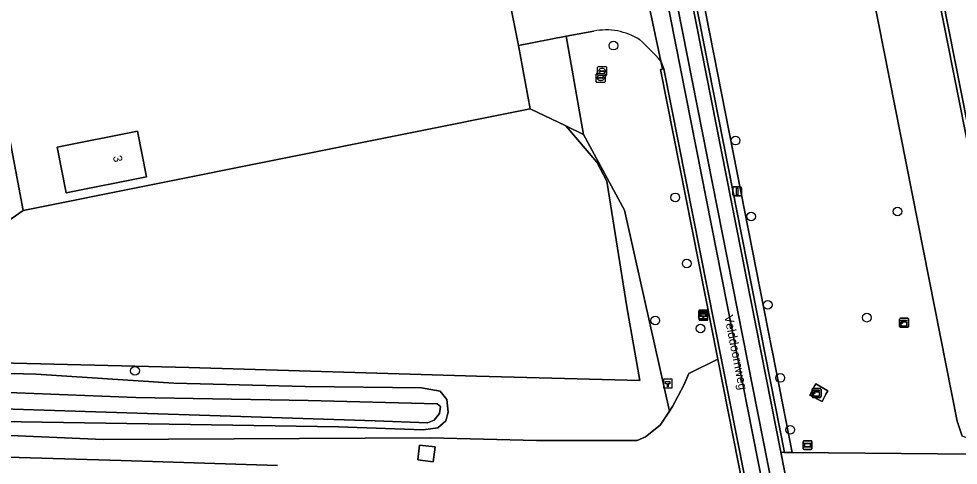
# Model space of a CAD drawing. Extents: x 160203 to 161530, y 379528 to 381797.
# Drawn here: x 160889.3 to 160995.1, y 379661.9 to 379712.2 of the extents above; entities that cross this region are included whole.
import ezdxf

# ---------------------------------------------------------------- set-up
doc = ezdxf.new("R2010")
doc.units = 0
for name, color, linetype in [('IMGEO_Berm_open', 7, 'Continuous'), ('IMGEO_Boom', 7, 'Continuous'), ('IMGEO_Brandkraan', 7, 'Continuous'), ('IMGEO_Erf', 7, 'Continuous'), ('IMGEO_Fietspad_open', 7, 'Continuous'), ('IMGEO_Grasland_overig', 7, 'Continuous'), ('IMGEO_Groenvoorziening', 7, 'Continuous'), ('IMGEO_Hectometerpaal', 7, 'Continuous'), ('IMGEO_Hek', 7, 'Continuous'), ('IMGEO_Kast', 7, 'Continuous'), ('IMGEO_Lichtmast', 7, 'Continuous'), ('IMGEO_Loofbos', 7, 'Continuous'), ('IMGEO_Openbare_ruimte_label', 7, 'Continuous'), ('IMGEO_Pand', 7, 'Continuous'), ('IMGEO_Pand_nummerreeks', 7, 'Continuous'), ('IMGEO_Rijbaan_lokaal_gesloten', 7, 'Continuous'), ('IMGEO_Rijbaan_lokaal_open', 7, 'Continuous'), ('IMGEO_Voetpad_open', 7, 'Continuous'), ('IMGEO_Wegwijzer', 7, 'Continuous')]:
    doc.layers.add(name, color=color, linetype=linetype)

msp = doc.modelspace()

# ---------------------------------------------------------------- linework, layer by layer
at = {"layer": 'IMGEO_Berm_open'}
for points in [[(160977.01, 379644.98), (160931.19, 379877.16)], [(160930.17, 379876.91), (160975.99, 379644.84)]]:
    msp.add_lwpolyline(points, dxfattribs=at)
at = {"layer": 'IMGEO_Boom'}
for centre in [(160956.25, 379709.18), (160970.01, 379698.49), (160963.22, 379692.1), (160988.22, 379690.51), (160971.76, 379689.95), (160964.5, 379684.65), (160973.62, 379680.01), (160960.97, 379678.24), (160984.77, 379678.56), (160966.06, 379677.33), (160902.4, 379672.57), (160975.04, 379671.77), (160976.16, 379665.93)]:
    msp.add_circle(centre, 0.489, dxfattribs=at)
at = {"layer": 'IMGEO_Brandkraan'}
for p, q in [((160954.48, 379705.89), (160954.48, 379706.75)), ((160954.56, 379706.82), (160955.41, 379706.82)), ((160955.48, 379706.75), (160955.48, 379705.89)), ((160954.32, 379705.12), (160954.32, 379705.98)), ((160954.39, 379706.05), (160955.25, 379706.05)), ((160955.41, 379705.82), (160954.56, 379705.82)), ((160954.74, 379706.31), (160954.74, 379706.33)), ((160955.18, 379706.28), (160954.78, 379706.28)), ((160954.79, 379706.36), (160955.18, 379706.36)), ((160954.81, 379705.83), (160954.83, 379705.83)), ((160954.97, 379706.6), (160955, 379706.6)), ((160954.99, 379706.04), (160954.97, 379706.04)), ((160955.23, 379706.33), (160955.23, 379706.31)), ((160955.32, 379705.98), (160955.32, 379705.12)), ((160955.25, 379705.05), (160954.39, 379705.05)), ((160954.58, 379705.54), (160954.58, 379705.56)), ((160954.62, 379705.59), (160955.02, 379705.59)), ((160955.01, 379705.51), (160954.62, 379705.51)), ((160954.83, 379705.27), (160954.8, 379705.27)), ((160955.06, 379705.56), (160955.06, 379705.54))]:
    msp.add_line(p, q, dxfattribs=at)
for points in [[(160954.48, 379705.89), (160954.48, 379706.75)], [(160954.56, 379706.82), (160955.41, 379706.82)], [(160955.48, 379706.75), (160955.48, 379705.89)], [(160954.32, 379705.12), (160954.32, 379705.98)], [(160954.39, 379706.05), (160955.25, 379706.05)], [(160955.41, 379705.82), (160954.56, 379705.82)], [(160955.32, 379705.98), (160955.32, 379705.12)], [(160955.25, 379705.05), (160954.39, 379705.05)]]:
    msp.add_lwpolyline(points, dxfattribs=at)
for centre, radius, start, end in [((160954.56, 379706.74), 0.0765, 91.552, 178.448), ((160954.56, 379706.74), 0.0765, 91.552, 178.448), ((160955.41, 379706.74), 0.0765, 1.552, 88.448), ((160955.41, 379706.74), 0.0765, 1.552, 88.448), ((160954.39, 379705.98), 0.0765, 91.552, 178.448), ((160954.39, 379705.98), 0.0765, 91.552, 178.448), ((160954.56, 379705.89), 0.0765, 181.552, 268.448), ((160954.56, 379705.89), 0.0765, 181.552, 268.448), ((160954.78, 379706.32), 0.0403, 85.8775, 175.7526), ((160954.78, 379706.31), 0.0366, 178.938, 274.7102), ((160955.19, 379706.32), 0.0386, 1.7309, 96.639), ((160955.18, 379706.32), 0.043, 264.8664, 352.4533), ((160955.24, 379705.98), 0.0765, 1.552, 88.448), ((160955.24, 379705.98), 0.0765, 1.552, 88.448), ((160955.41, 379705.89), 0.0765, 271.552, 358.448), ((160955.41, 379705.89), 0.0765, 271.552, 358.448), ((160954.39, 379705.13), 0.0765, 181.552, 268.448), ((160954.39, 379705.13), 0.0765, 181.552, 268.448), ((160954.62, 379705.55), 0.0403, 85.8775, 175.7526), ((160954.61, 379705.54), 0.0366, 178.938, 274.7102), ((160955.02, 379705.55), 0.043, 264.8664, 352.4533), ((160955.02, 379705.56), 0.0386, 1.7309, 96.639), ((160955.24, 379705.13), 0.0765, 271.552, 358.448), ((160955.24, 379705.13), 0.0765, 271.552, 358.448)]:
    msp.add_arc(centre, radius, start, end, dxfattribs=at)
for centre, major_axis, ratio, start_param, end_param in [((160954.81, 379705.55), (-0.387, 0.002), 0.722429, 4.712389, 7.853982), ((160954.97, 379706.32), (-0.387, 0.002), 0.722429, 4.712389, 7.853982), ((160954.83, 379705.55), (-0.39, 0.002), 0.717154, 1.570796, 4.712389), ((160954.99, 379706.32), (-0.39, 0.002), 0.717154, 1.570796, 4.712389)]:
    msp.add_ellipse(centre, major_axis=major_axis, ratio=ratio, start_param=start_param, end_param=end_param, dxfattribs=at)
at = {"layer": 'IMGEO_Erf'}
for points in [[(160945.57, 379709.21), (160944.72, 379713.51), (160938.84, 379743.37), (160882.02, 379731.98), (160889.82, 379690.64), (160946.9, 379702.08)], [(160894.67, 379692.62), (160893.65, 379697.75), (160902.69, 379699.55), (160903.71, 379694.42)]]:
    msp.add_lwpolyline(points, close=True, dxfattribs=at)
at = {"layer": 'IMGEO_Fietspad_open'}
msp.add_lwpolyline([(161063.74, 379662.75), (161006.45, 379663.11), (161000.99, 379663.16), (160976.37, 379663.39), (160975.52, 379663.39), (160975.09, 379663.4), (160975.92, 379659.23), (160976.32, 379659.23), (160998.67, 379659.17), (161063.76, 379658.82)], dxfattribs=at)
at = {"layer": 'IMGEO_Grasland_overig'}
for points in [[(161089.29, 379874.82), (161088.06, 379883.66), (161097.99, 379885.6), (161095.06, 379898.6), (161067.76, 379903.29), (161066.72, 379897.25), (161064.96, 379897.55), (161064.27, 379901.09), (161048.67, 379898.05), (161049.44, 379894.12), (161037.66, 379891.83), (161037.23, 379894.01), (161021.55, 379891.08), (161008.69, 379888.67), (161005.82, 379890.02), (161000, 379888.88), (160960.29, 379881.14), (160984.65, 379758.21), (161001.9, 379671.16), (161088.81, 379688.39), (161124.8, 379695.53), (161114.01, 379750)], [(160934.22, 379662.54), (160934.42, 379664.21), (160936.18, 379664), (160935.97, 379662.32)]]:
    msp.add_lwpolyline(points, close=True, dxfattribs=at)
for points in [[(160840.36, 379818.7), (160816.73, 379790.12), (160856.72, 379758.62), (160866.07, 379730.92), (160881.55, 379684.93), (160889.82, 379690.64), (160882.02, 379731.98), (160938.84, 379743.37), (160943.64, 379744.33), (160939.89, 379764.64), (160934.91, 379791.64)], [(160971.5, 379656.22), (160968, 379673.87), (160964.76, 379672.27), (160964.17, 379670.97), (160962.9, 379668.56), (160962.56, 379668.04), (160961.52, 379666.45), (160959.86, 379665.14), (160958.91, 379664.75), (160947.59, 379664.74), (160935.67, 379665.03), (160898.81, 379664.84), (160883.98, 379665.5), (160868.89, 379665.98), (160828.06, 379666.96), (160812.93, 379667.08), (160784.17, 379667.9), (160765.94, 379668.23)], [(160768.72, 379665.89), (160783.83, 379665.68), (160798.49, 379665.21), (160840.84, 379664.24), (160900.83, 379662.49), (160918.44, 379661.9)]]:
    msp.add_lwpolyline(points, dxfattribs=at)
at = {"layer": 'IMGEO_Groenvoorziening'}
for points in [[(161124.8, 379695.53), (161088.81, 379688.39), (161001.9, 379671.16), (160984.65, 379758.21), (160960.29, 379881.14), (160959.82, 379881.05), (160959.92, 379880.51), (160960.04, 379879.9), (160973.15, 379813.39), (160984.11, 379758.57), (160985.83, 379750), (161000, 379678.61), (161001.69, 379670.67), (161089.34, 379688.04), (161125.46, 379695.28), (161122.82, 379708.52), (161121.99, 379712.67), (161114.55, 379750), (161114.01, 379750)], [(160933, 379878.98), (160975.52, 379663.39), (160976.37, 379663.39), (160974.15, 379674.69), (160974.08, 379675.03), (160933.99, 379879.07)], [(160980.18, 379669.95), (160979.75, 379669.14), (160978.36, 379669.85), (160978.94, 379670.92), (160979.04, 379671.1), (160980.4, 379670.34)]]:
    msp.add_lwpolyline(points, close=True, dxfattribs=at)
for points in [[(160933.99, 379879.07), (160974.08, 379675.03), (160974.15, 379674.69), (160976.37, 379663.39), (161000.99, 379663.16), (161006.45, 379663.11), (161063.74, 379662.75)], [(161142.92, 379692.64), (161145.98, 379696.54), (161138.27, 379693.24), (161136.23, 379692.23), (161130.68, 379689.47), (161118.14, 379687.03), (161106.5, 379683.85), (161096.48, 379679.04), (161085.04, 379672.67), (161070.4, 379668.01), (161059.14, 379666.39), (161049.4, 379665.53), (161034.57, 379663.65), (161025.83, 379663.99), (161019.86, 379665.34), (161017.76, 379665.27), (161013.76, 379664.34), (161011.91, 379663.38), (161000.99, 379663.27), (160995.51, 379665.23), (160994.95, 379666.91), (160953.02, 379879)], [(160954.03, 379710.81), (160950.95, 379710.23), (160952.89, 379699.18), (160957.49, 379690.67), (160962.56, 379668.04), (160962.9, 379668.56), (160964.17, 379670.97), (160964.76, 379672.27), (160968, 379673.87), (160961.55, 379706.48)], [(160961.55, 379706.48), (160961.79, 379706.53), (160961.6, 379707.42)], [(160883.98, 379665.5), (160898.81, 379664.84), (160935.67, 379665.03), (160947.59, 379664.74), (160958.91, 379664.75), (160959.86, 379665.14), (160961.52, 379666.45), (160962.56, 379668.04), (160957.49, 379690.67), (160952.89, 379699.18), (160950.89, 379700.14), (160954.39, 379696.07), (160955.51, 379693.91), (160957.77, 379679.76), (160959.24, 379671.47), (160940.83, 379671.98), (160908.47, 379672.95), (160882.6, 379673.6)], [(160758.24, 379671.16), (160779.42, 379670.28), (160787.45, 379670.4), (160800.46, 379670.24), (160856, 379668.81), (160885.15, 379668.38), (160929.42, 379666.96), (160935.32, 379666.72), (160936.09, 379667.02), (160936.67, 379667.77), (160936.8, 379668.56), (160936.41, 379668.85), (160921.88, 379669.22), (160902.49, 379669.56), (160883.33, 379670.33), (160865.8, 379671.12), (160822.07, 379671.95), (160792.15, 379672.79), (160782.51, 379673.2), (160766.24, 379673.54)], [(160766.24, 379673.54), (160782.51, 379673.2), (160792.15, 379672.79), (160822.07, 379671.95), (160865.8, 379671.12), (160883.33, 379670.33), (160902.49, 379669.56), (160921.88, 379669.22), (160936.41, 379668.85), (160936.8, 379668.56), (160936.67, 379667.77), (160936.09, 379667.02), (160935.32, 379666.72), (160929.42, 379666.96), (160885.15, 379668.38), (160856, 379668.81), (160800.46, 379670.24), (160787.45, 379670.4), (160779.42, 379670.28), (160758.24, 379671.16)], [(160842.51, 379673.48), (160891.29, 379672.2), (160906.77, 379671.18), (160921.57, 379670.82), (160934.64, 379670.66), (160936.75, 379670.28), (160937.49, 379669.34), (160937.67, 379667.93), (160937.38, 379666.93), (160936.5, 379666.16), (160934.84, 379665.92), (160925.29, 379666.27), (160875.27, 379667.07)], [(160875.27, 379667.07), (160925.29, 379666.27), (160934.84, 379665.92), (160936.5, 379666.16), (160937.38, 379666.93), (160937.67, 379667.93), (160937.49, 379669.34), (160936.75, 379670.28), (160934.64, 379670.66), (160921.57, 379670.82), (160906.77, 379671.18), (160891.29, 379672.2), (160842.51, 379673.48)], [(160918.44, 379661.9), (160900.83, 379662.49), (160840.84, 379664.24), (160798.49, 379665.21), (160783.83, 379665.68), (160768.72, 379665.89)]]:
    msp.add_lwpolyline(points, dxfattribs=at)
for centre, radius, start, end in [((160955.42, 379703.88), 7.07, 57.5977, 101.3115), ((160942.12, 379690.63), 25.72, 40.7712, 48.3733)]:
    msp.add_arc(centre, radius, start, end, dxfattribs=at)
at = {"layer": 'IMGEO_Hectometerpaal'}
for p, q in [((160966.79, 379679.26), (160965.95, 379679.26)), ((160966.79, 379679.26), (160965.95, 379679.26)), ((160965.88, 379679.17), (160965.88, 379678.33)), ((160965.88, 379679.17), (160965.88, 379678.33)), ((160965.96, 379678.26), (160966.8, 379678.26)), ((160965.96, 379678.26), (160966.8, 379678.26)), ((160966.88, 379678.34), (160966.88, 379679.18)), ((160966.88, 379678.34), (160966.88, 379679.18)), ((160961.88, 379671.57), (160961.88, 379670.72)), ((160961.88, 379671.57), (160961.88, 379670.72)), ((160962.79, 379671.65), (160961.95, 379671.65)), ((160962.79, 379671.65), (160961.95, 379671.65)), ((160962.88, 379670.73), (160962.88, 379671.58)), ((160962.88, 379670.73), (160962.88, 379671.58)), ((160961.96, 379670.65), (160962.8, 379670.65)), ((160961.96, 379670.65), (160962.8, 379670.65))]:
    msp.add_line(p, q, dxfattribs=at)
for points in [[(160966.4, 379678.4), (160966.34, 379678.4), (160966.34, 379678.71), (160966.12, 379678.71), (160966.12, 379678.98), (160966.62, 379678.98), (160966.62, 379678.71), (160966.4, 379678.71), (160966.4, 379678.4)], [(160962.4, 379670.79), (160962.34, 379670.79), (160962.34, 379671.1), (160962.12, 379671.1), (160962.12, 379671.37), (160962.62, 379671.37), (160962.62, 379671.1), (160962.4, 379671.1), (160962.4, 379670.79)]]:
    msp.add_lwpolyline(points, dxfattribs=at)
for centre, start, end in [((160965.96, 379679.18), 92.4484, 184.2845), ((160965.96, 379679.18), 92.4484, 184.2845), ((160966.8, 379679.18), 2.4484, 94.2845), ((160966.8, 379679.18), 2.4484, 94.2845), ((160965.96, 379678.34), 182.4484, 274.2845), ((160965.96, 379678.34), 182.4484, 274.2845), ((160966.8, 379678.34), 272.4484, 4.2845), ((160966.8, 379678.34), 272.4484, 4.2845), ((160961.96, 379671.57), 92.4484, 184.2845), ((160961.96, 379671.57), 92.4484, 184.2845), ((160962.8, 379671.57), 2.4484, 94.2845), ((160962.8, 379671.57), 2.4484, 94.2845), ((160961.96, 379670.73), 182.4484, 274.2845), ((160961.96, 379670.73), 182.4484, 274.2845), ((160962.8, 379670.73), 272.4484, 4.2845), ((160962.8, 379670.73), 272.4484, 4.2845)]:
    msp.add_arc(centre, 0.0779, start, end, dxfattribs=at)
at = {"layer": 'IMGEO_Hek'}
for points in [[(161000, 379678.61), (160985.83, 379750)], [(160889.82, 379690.64), (160882.02, 379731.98), (160938.84, 379743.37)], [(160944.72, 379713.51), (160945.57, 379709.21)], [(160946.9, 379702.08), (160945.57, 379709.21)], [(160946.9, 379702.08), (160889.82, 379690.64)], [(160950.89, 379700.14), (160946.9, 379702.08)], [(160940.83, 379671.98), (160959.24, 379671.47), (160957.77, 379679.76), (160955.51, 379693.91), (160954.39, 379696.07), (160950.89, 379700.14)], [(160940.83, 379671.98), (160908.47, 379672.95), (160882.6, 379673.6), (160881.21, 379673.45), (160879.82, 379672.97), (160869.97, 379673.11), (160857.9, 379673.43), (160844.53, 379673.94), (160833.38, 379673.96), (160827.65, 379674.08)]]:
    msp.add_lwpolyline(points, dxfattribs=at)
at = {"layer": 'IMGEO_Kast'}
for p, q in [((160988.47, 379677.56), (160988.47, 379678.4)), ((160988.47, 379678.4), (160988.47, 379677.56)), ((160988.54, 379678.49), (160989.38, 379678.49)), ((160989.38, 379678.49), (160988.54, 379678.49)), ((160989.47, 379678.41), (160989.47, 379677.57)), ((160989.47, 379677.57), (160989.47, 379678.41)), ((160989.39, 379677.49), (160988.55, 379677.49)), ((160988.55, 379677.49), (160989.39, 379677.49)), ((160978.62, 379669.66), (160978.62, 379670.5)), ((160978.62, 379670.5), (160978.62, 379669.66)), ((160978.7, 379670.59), (160979.54, 379670.59)), ((160979.54, 379670.59), (160978.7, 379670.59)), ((160979.62, 379670.51), (160979.62, 379669.67)), ((160979.62, 379669.67), (160979.62, 379670.51)), ((160979.55, 379669.59), (160978.71, 379669.59)), ((160978.71, 379669.59), (160979.55, 379669.59))]:
    msp.add_line(p, q, dxfattribs=at)
for points in [[(160988.66, 379678.28), (160989.26, 379678.28), (160989.26, 379678.19), (160988.66, 379678.19), (160988.66, 379678.28)], [(160988.66, 379678.1), (160989.26, 379678.1), (160989.26, 379677.61), (160988.66, 379677.61), (160988.66, 379678.1)], [(160978.82, 379670.38), (160979.42, 379670.38), (160979.42, 379670.29), (160978.82, 379670.29), (160978.82, 379670.38)], [(160978.82, 379670.2), (160979.42, 379670.2), (160979.42, 379669.71), (160978.82, 379669.71), (160978.82, 379670.2)]]:
    msp.add_lwpolyline(points, dxfattribs=at)
for centre in [(160988.75, 379677.95), (160978.9, 379670.05)]:
    msp.add_circle(centre, 0.0377, dxfattribs=at)
for centre, start, end in [((160988.55, 379678.41), 92.4484, 184.2845), ((160988.55, 379678.41), 92.4484, 184.2845), ((160989.39, 379678.41), 2.4484, 94.2845), ((160989.39, 379678.41), 2.4484, 94.2845), ((160988.55, 379677.57), 182.4484, 274.2845), ((160988.55, 379677.57), 182.4484, 274.2845), ((160989.39, 379677.57), 272.4484, 4.2845), ((160989.39, 379677.57), 272.4484, 4.2845), ((160978.7, 379670.51), 92.4484, 184.2845), ((160978.7, 379670.51), 92.4484, 184.2845), ((160979.54, 379670.51), 2.4484, 94.2845), ((160979.54, 379670.51), 2.4484, 94.2845), ((160978.7, 379669.66), 182.4484, 274.2845), ((160978.7, 379669.66), 182.4484, 274.2845), ((160979.54, 379669.66), 272.4484, 4.2845), ((160979.54, 379669.66), 272.4484, 4.2845)]:
    msp.add_arc(centre, 0.0779, start, end, dxfattribs=at)
at = {"layer": 'IMGEO_Lichtmast'}
for p, q in [((160969.68, 379692.38), (160969.68, 379693.18)), ((160969.68, 379693.18), (160969.68, 379692.38)), ((160969.78, 379693.28), (160970.57, 379693.28)), ((160970.57, 379693.28), (160969.78, 379693.28)), ((160970.67, 379693.18), (160970.67, 379692.38)), ((160970.67, 379692.38), (160970.67, 379693.18)), ((160970.57, 379692.28), (160969.78, 379692.28)), ((160969.78, 379692.28), (160970.57, 379692.28))]:
    msp.add_line(p, q, dxfattribs=at)
msp.add_lwpolyline([(160970.1, 379693.15), (160970.25, 379693.15), (160970.25, 379692.4), (160970.1, 379692.4), (160970.1, 379693.15)], dxfattribs=at)
for centre, start, end in [((160969.78, 379693.18), 90, 180), ((160969.78, 379693.18), 90, 180), ((160970.57, 379693.18), 0, 90), ((160970.57, 379693.18), 360, 90), ((160969.78, 379692.38), 180, 270), ((160969.78, 379692.38), 180, 270), ((160970.57, 379692.38), 270, 0), ((160970.57, 379692.38), 270, 0)]:
    msp.add_arc(centre, 0.1, start, end, dxfattribs=at)
at = {"layer": 'IMGEO_Loofbos'}
for points in [[(160953.02, 379879), (160994.95, 379666.91), (160995.51, 379665.23)], [(161000, 379678.61), (160985.83, 379750), (160984.11, 379758.57), (160973.15, 379813.39)]]:
    msp.add_lwpolyline(points, dxfattribs=at)
for points in [[(160946.9, 379702.08), (160950.89, 379700.14), (160952.89, 379699.18), (160950.95, 379710.23), (160945.57, 379709.21)], [(160881.55, 379684.93), (160827.65, 379674.08), (160833.38, 379673.96), (160844.53, 379673.94), (160857.9, 379673.43), (160869.97, 379673.11), (160879.82, 379672.97), (160881.21, 379673.45), (160882.6, 379673.6), (160908.47, 379672.95), (160940.83, 379671.98), (160959.24, 379671.47), (160957.77, 379679.76), (160955.51, 379693.91), (160954.39, 379696.07), (160950.89, 379700.14), (160946.9, 379702.08), (160889.82, 379690.64)]]:
    msp.add_lwpolyline(points, close=True, dxfattribs=at)
at = {"layer": 'IMGEO_Pand'}
msp.add_lwpolyline([(160894.67, 379692.62), (160903.71, 379694.42), (160902.69, 379699.55), (160893.65, 379697.75)], close=True, dxfattribs=at)
at = {"layer": 'IMGEO_Rijbaan_lokaal_gesloten'}
for points in [[(160975.92, 379659.23), (160975.09, 379663.4), (160924.29, 379920.91)], [(160931.19, 379877.16), (160977.01, 379644.98)], [(160928.42, 379876.71), (160946.01, 379787.18), (160958.42, 379724.61), (160958.86, 379722.38), (160958.7, 379722.31), (160958.76, 379721.91), (160958.63, 379721.42), (160961.6, 379707.42), (160961.94, 379706.57), (160974.23, 379644.48)], [(160975.99, 379644.84), (160930.17, 379876.91)]]:
    msp.add_lwpolyline(points, dxfattribs=at)
at = {"layer": 'IMGEO_Rijbaan_lokaal_open'}
for points in [[(160924.7, 379921.2), (160923.56, 379926.8), (160923.14, 379926.74), (160924.29, 379920.91), (160975.09, 379663.4), (160975.52, 379663.39), (160933, 379878.98), (160932.65, 379880.98), (160932.53, 379881.6), (160924.74, 379920.98)], [(160961.6, 379707.42), (160961.79, 379706.53), (160961.55, 379706.48), (160968, 379673.87), (160971.5, 379656.22), (160973.83, 379644.43), (160973.83, 379644.42), (160974.23, 379644.48), (160961.94, 379706.57)]]:
    msp.add_lwpolyline(points, close=True, dxfattribs=at)
for points in [[(160961.6, 379707.42), (160958.63, 379721.42)], [(160952.04, 379715.05), (160950.07, 379714.63), (160944.72, 379713.51), (160945.57, 379709.21), (160950.95, 379710.23), (160954.03, 379710.81)]]:
    msp.add_lwpolyline(points, dxfattribs=at)
for centre, radius, start, end in [((160955.42, 379703.88), 7.07, 57.5977, 101.3115), ((160942.12, 379690.63), 25.72, 40.7712, 48.3733)]:
    msp.add_arc(centre, radius, start, end, dxfattribs=at)
at = {"layer": 'IMGEO_Voetpad_open'}
for points in [[(160980.4, 379670.34), (160979.04, 379671.1), (160978.94, 379670.92), (160978.36, 379669.85), (160979.75, 379669.14), (160980.18, 379669.95)], [(160936.18, 379664), (160934.42, 379664.21), (160934.22, 379662.54), (160935.97, 379662.32)]]:
    msp.add_lwpolyline(points, close=True, dxfattribs=at)
at = {"layer": 'IMGEO_Wegwijzer'}
for p, q in [((160965.87, 379678.52), (160965.87, 379679.32)), ((160965.87, 379679.32), (160965.87, 379678.52)), ((160965.97, 379679.42), (160966.76, 379679.42)), ((160966.76, 379679.42), (160965.97, 379679.42)), ((160966.86, 379679.32), (160966.86, 379678.52)), ((160966.86, 379678.52), (160966.86, 379679.32)), ((160966.76, 379678.42), (160965.97, 379678.42)), ((160965.97, 379678.42), (160966.76, 379678.42)), ((160977.61, 379663.81), (160977.61, 379664.61)), ((160977.61, 379664.61), (160977.61, 379663.81)), ((160977.71, 379664.71), (160978.5, 379664.71)), ((160978.5, 379664.71), (160977.71, 379664.71)), ((160978.6, 379664.61), (160978.6, 379663.81)), ((160978.6, 379663.81), (160978.6, 379664.61)), ((160978.5, 379663.71), (160977.71, 379663.71)), ((160977.71, 379663.71), (160978.5, 379663.71))]:
    msp.add_line(p, q, dxfattribs=at)
for points in [[(160965.97, 379679.15), (160966.75, 379679.15), (160966.75, 379678.69), (160965.97, 379678.69), (160965.97, 379679.15)], [(160966.03, 379679.09), (160966.03, 379678.75), (160966.69, 379678.75), (160966.69, 379679.09), (160966.03, 379679.09)], [(160977.71, 379664.44), (160978.5, 379664.44), (160978.5, 379663.97), (160977.71, 379663.97), (160977.71, 379664.44)], [(160977.78, 379664.37), (160977.78, 379664.04), (160978.43, 379664.04), (160978.43, 379664.37), (160977.78, 379664.37)]]:
    msp.add_lwpolyline(points, dxfattribs=at)
for centre, start, end in [((160965.97, 379679.32), 90, 180), ((160965.97, 379679.32), 90, 180), ((160966.76, 379679.32), 0, 90), ((160966.76, 379679.32), 360, 90), ((160965.97, 379678.52), 180, 270), ((160965.97, 379678.52), 180, 270), ((160966.76, 379678.52), 270, 0), ((160966.76, 379678.52), 270, 0), ((160977.71, 379664.61), 90, 180), ((160977.71, 379664.61), 90, 180), ((160978.5, 379664.61), 0, 90), ((160978.5, 379664.61), 360, 90), ((160977.71, 379663.81), 180, 270), ((160977.71, 379663.81), 180, 270), ((160978.5, 379663.81), 270, 0), ((160978.5, 379663.81), 270, 0)]:
    msp.add_arc(centre, 0.1, start, end, dxfattribs=at)

# ---------------------------------------------------------------- texts
at = {"layer": 'IMGEO_Openbare_ruimte_label'}
msp.add_text('Velddoornweg', height=1, rotation=281.2987, dxfattribs=at).set_placement((160968.72, 379678.74))
at = {"layer": 'IMGEO_Pand_nummerreeks'}
msp.add_text('3', height=1, rotation=281.261, dxfattribs=at).set_placement((160899.91, 379696.72))

doc.saveas('drawing.dxf')
